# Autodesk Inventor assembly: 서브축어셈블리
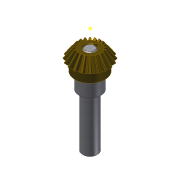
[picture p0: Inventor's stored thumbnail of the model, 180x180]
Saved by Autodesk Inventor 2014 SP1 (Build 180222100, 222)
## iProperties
Created: 2014-10
Part Number: 서브축어셈블리
Document SubType Name: Assembly
Designer: KYOUNG IL JANG
Author: KYOUNG IL JANG
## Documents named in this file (5)
- D:\20_MDU\10_기술자격시험\20_Inventor\2014-10월 출제중\2급\서브축어셈블리.iam
- D:\20_MDU\10_기술자격시험\20_Inventor\2014-10월 출제중\2급\서브 베벨기어.ipt
- D:\20_MDU\10_기술자격시험\20_Inventor\2014-10월 출제중\2급\서브 축.ipt
- 서브 축.ipt
- D:\20_MDU\10_기술자격시험\20_Inventor\2014-10월 출제중\2급\키 4x4.ipt
